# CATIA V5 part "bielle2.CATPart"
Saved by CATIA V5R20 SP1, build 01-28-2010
Part number: bielle2
Bounding box of the stored display mesh (mm): x 0 to 10, y 42.442 to 132.899, z -74.708 to -7.266
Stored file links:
  E:\EDELI\gcausse\Edeli_2012_681_gcausse\bielle2.CATPart
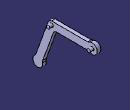
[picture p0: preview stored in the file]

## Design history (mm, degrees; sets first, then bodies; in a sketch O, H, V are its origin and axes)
Body1 (main body)
  Sketch1 on yz-plane, origin (0, 0, 0), H (0, 1, 0), V (0, 0, 1)
    line L1 (121.0003, -9.1829) -> (65.4129, -9.1829)
    point P2 (65.4129, -9.1829)
    line L2 (121.0003, -19.1829) -> (72.415, -19.1829)
    point P4 (72.415, -19.1829)
    line L3 (72.415, -19.1829) -> (55.7979, -64.8382)
    line L4 (65.4129, -9.1829) -> (46.4009, -61.418)
    arc A1 centre (49.4239, -67.7316) radius 7 from (46.4009, -61.418) to (55.7979, -64.8382) ccw
    point P7 (49.4239, -67.7316)
    arc A2 centre (125.8993, -14.1829) radius 7 from (121.0003, -9.1829) to (121.0003, -19.1829) cw
    point P8 (125.8993, -14.1829)
    circle A3 centre (68.914, -14.1829) radius 2.5
    point P9 (68.914, -14.1829)
    radius A3 = 2.5
    radius A2 = 7
    radius A1 = 7
    angle L4 L1 = 70
    distance L3 L4 = 10
    distance L1 L2 = 10
    distance P8 L2 = 5
    distance P7 L3 = 5
    distance P7 P9 = 56.9853 {= 50mm*1.55/1.36}
    horizontal: L1 H, L2 H
    equidistance: P2 P4 P9, L3 L4 P9, P7 P8 P9
  Pad1: profile Sketch1, direction (1, 0, 0), length 5
  Sketch2 on end face of Pad1, origin (5, 0, 0), H (0, 1, 0), V (0, 0, 1)
    circle A1 centre (68.914, -14.1829) radius 2.5
    reference projected circle E1 centre (68.914, -14.1829) radius 2.5 from edge [end face of Pad1 | face of Pad1 from Sketch1.A3]
    reference projected circle E2 centre (68.914, -14.1829) radius 2.5 from edge [end face of Pad1 | face of Pad1 from Sketch1.A3]
    radius A1 = 2.5
    radius E2 = 2.5 (reference)
    concentricity: A1 E1
  Pad2: profile Sketch2, direction (-1, 0, 0), length 5
  Sketch3 on start face of Pad1, origin (0, 0, 0), H (0, -1, 0), V (0, 0, 1)
    circle A1 centre (-125.8993, -14.1829) radius 2.5
    reference projected arc E1 centre (-125.8993, -14.1829) radius 7 from (-121.0003, -9.1829) to (-121.0003, -19.1829) ccw from edge [start face of Pad1 | face of Pad1 from Sketch1.A2]
    reference projected arc E2 centre (-125.8993, -14.1829) radius 7 from (-121.0003, -9.1829) to (-121.0003, -19.1829) ccw from edge [start face of Pad1 | face of Pad1 from Sketch1.A2]
    radius A1 = 2.5
    radius E2 = 7 (reference)
    concentricity: A1 E1
  Pad3: profile Sketch3, direction (-1, 0, 0), length -10
  Fillet1: radius 5, on edge [face of Pad1 from Sketch1.L4 | face of Pad1 from Sketch1.L1]; edge [face of Pad1 from Sketch1.L1 | face of Pad1 from Sketch1.A2]; edge [face of Pad1 from Sketch1.A2 | face of Pad1 from Sketch1.L2]; edge [face of Pad1 from Sketch1.L2 | face of Pad1 from Sketch1.L3]; edge [face of Pad1 from Sketch1.L3 | face of Pad1 from Sketch1.A1]; edge [face of Pad1 from Sketch1.A1 | face of Pad1 from Sketch1.L4]
  Sketch4 on face of Pad2, origin (5, 0, 0), H (0, 1, 0), V (0, 0, 1)
    circle A1 centre (68.914, -14.1829) radius 2.5
    point P1 (68.914, -14.1829)
    reference projected line E1 (55.7979, -64.8382) -> (72.415, -19.1829) from edge [face of Pad1 from Sketch1.L3 | face of Pad2]
    reference projected line E2 (65.4129, -9.1829) -> (46.4009, -61.418) from edge [face of Pad1 from Sketch1.L4 | face of Pad2]
    reference projected line E3 (121.0003, -9.1829) -> (65.4129, -9.1829) from edge [face of Pad1 from Sketch1.L1 | face of Pad2]
    reference projected line E4 (72.415, -19.1829) -> (121.0003, -19.1829) from edge [face of Pad1 from Sketch1.L2 | face of Pad2]
    radius A1 = 2.5
    equidistance: E1 E2 P1, E3 E4 P1
  Pad4: profile Sketch4, direction (1, 0, 0), length 5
